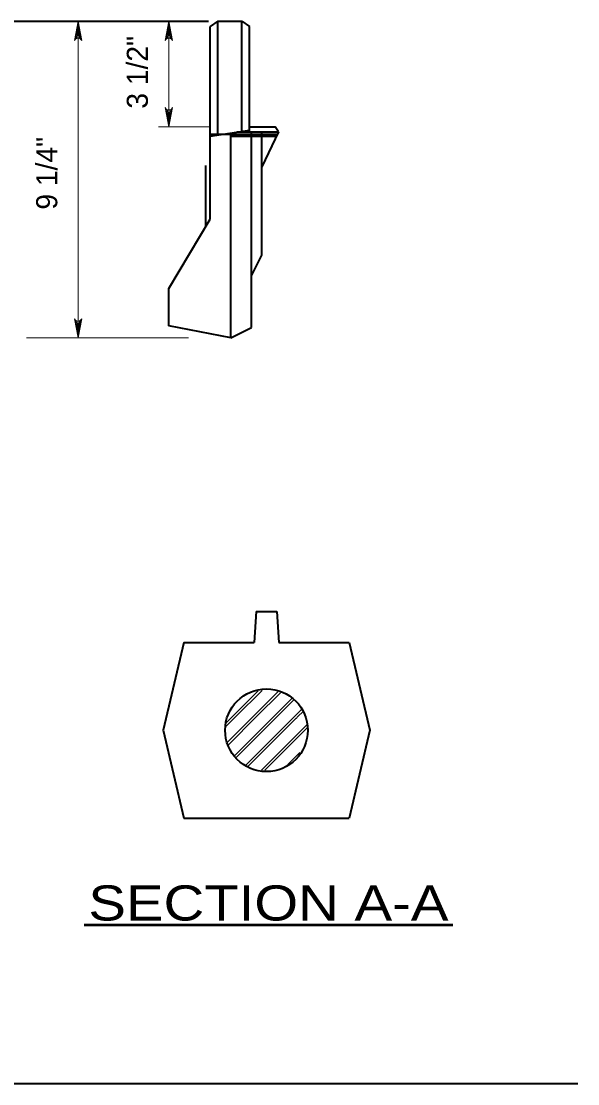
# Model space of a CAD drawing. Extents: x 15 to 140, y -57 to 117.
# Drawn here: x 113.5 to 140.4, y 57.9 to 109.4 of the extents above; entities that cross this region are included whole.
import ezdxf
from ezdxf.enums import TextEntityAlignment as Align

# ---------------------------------------------------------------- set-up
doc = ezdxf.new("R2010")
doc.units = 0
doc.header["$LTSCALE"] = 0.41
for name, color, linetype, lineweight in [('1', 7, 'Continuous', 35), ('10', 7, 'Continuous', 13), ('12', 7, 'Continuous', 53), ('13', 7, 'Continuous', 53), ('6', 7, 'Continuous', 13)]:
    doc.layers.add(name, color=color, linetype=linetype, lineweight=lineweight)

msp = doc.modelspace()

# ---------------------------------------------------------------- linework, layer by layer
at = {"layer": '1'}
for p, q in [((112.8121, 109.3527), (122.5672, 109.3527)), ((123.0195, 109.3532), (124.1695, 109.3532)), ((124.1695, 103.997), (124.1695, 109.3532)), ((124.1695, 109.3532), (124.5445, 109.1032)), ((124.5445, 103.997), (124.5445, 109.1032)), ((122.6445, 103.797), (124.5445, 104.0905)), ((122.6445, 103.897), (125.907, 103.897)), ((123.6445, 94.0282), (123.6445, 103.9515)), ((123.9389, 103.997), (125.955, 103.997)), ((124.5445, 104.247), (125.7917, 104.247)), ((124.6445, 94.5282), (124.6445, 103.997)), ((125.1445, 98.0282), (125.1445, 103.997)), ((125.955, 103.997), (125.1445, 102.3085)), ((125.955, 103.997), (125.7917, 104.247)), ((123.6445, 103.797), (125.859, 103.797)), ((122.4292, 99.4161), (122.4292, 102.3744)), ((120.6445, 96.415), (122.6445, 99.7782)), ((124.6445, 97.0282), (125.1445, 98.0282)), ((120.6445, 94.6114), (120.6445, 96.415)), ((123.6445, 94.0282), (120.6445, 94.6114)), ((123.6445, 94.0282), (124.6445, 94.5282)), ((124.8665, 80.799), (124.7665, 79.299)), ((124.8665, 80.799), (125.8665, 80.799)), ((125.8665, 80.799), (125.9665, 79.299)), ((121.3665, 79.299), (124.7665, 79.299)), ((125.9665, 79.299), (129.3665, 79.299)), ((121.3665, 70.799), (129.3665, 70.799)), ((140.4342, 57.946), (15.0728, 57.946))]:
    msp.add_line(p, q, dxfattribs=at)
for points in [[(123.0195, 103.897), (123.0195, 109.3532), (122.6445, 109.1032)], [(122.6445, 99.7782), (122.6445, 103.997), (122.6445, 109.1032)], [(121.3665, 79.299), (120.3665, 75.049), (121.3665, 70.799)], [(129.3665, 79.299), (130.3665, 75.049), (129.3665, 70.799)]]:
    msp.add_lwpolyline(points, dxfattribs=at)
msp.add_circle((125.3665, 75.049), 2, dxfattribs=at)
at = {"layer": '10'}
for p, q in [((116.2471, 94.0282), (116.2471, 109.3527)), ((120.6445, 104.247), (120.6445, 109.3527)), ((122.6445, 104.247), (120.1445, 104.247)), ((113.7471, 94.0282), (121.5976, 94.0282))]:
    msp.add_line(p, q, dxfattribs=at)
for points in [[(116.2471, 109.3527), (116.4219, 108.4206), (116.3721, 108.4924), (116.3096, 108.5294), (116.2471, 108.5402), (116.1846, 108.5294), (116.1221, 108.4924), (116.0723, 108.4206), (116.2471, 109.3527), (116.1221, 108.4924), (116.1846, 108.5294), (116.2471, 109.3527), (116.2471, 108.5402), (116.3096, 108.5294), (116.2471, 109.3527), (116.3721, 108.4924)], [(120.6445, 109.3527), (120.8193, 108.4206), (120.7695, 108.4924), (120.707, 108.5294), (120.6445, 108.5402), (120.582, 108.5294), (120.5195, 108.4924), (120.4697, 108.4206), (120.6445, 109.3527), (120.5195, 108.4924), (120.582, 108.5294), (120.6445, 109.3527), (120.6445, 108.5402), (120.707, 108.5294), (120.6445, 109.3527), (120.7695, 108.4924)], [(120.6445, 104.247), (120.4697, 105.179), (120.5195, 105.1072), (120.582, 105.0702), (120.6445, 105.0595), (120.707, 105.0702), (120.7695, 105.1072), (120.8193, 105.179), (120.6445, 104.247), (120.7695, 105.1072), (120.707, 105.0702), (120.6445, 104.247), (120.6445, 105.0595), (120.582, 105.0702), (120.6445, 104.247), (120.5195, 105.1072)], [(116.2471, 94.0282), (116.0723, 94.9603), (116.1221, 94.8885), (116.1846, 94.8514), (116.2471, 94.8407), (116.3096, 94.8514), (116.3721, 94.8885), (116.4219, 94.9603), (116.2471, 94.0282), (116.3721, 94.8885), (116.3096, 94.8514), (116.2471, 94.0282), (116.2471, 94.8407), (116.1846, 94.8514), (116.2471, 94.0282), (116.1221, 94.8885)]]:
    msp.add_lwpolyline(points, dxfattribs=at)
at = {"layer": '12'}
msp.add_line((116.5372, 65.6308), (134.3858, 65.6308), dxfattribs=at)
at = {"layer": '6'}
for p, q in [((123.7184, 75.7101), (124.9577, 76.9494)), ((123.8851, 75.7101), (125.1538, 76.9788)), ((124.7184, 75.7101), (125.9197, 76.9114)), ((124.8851, 75.7101), (126.0426, 76.8676)), ((125.7184, 75.7101), (126.5928, 76.5844)), ((125.8851, 75.7101), (126.6721, 76.4971)), ((123.4059, 75.3975), (123.7184, 75.7101)), ((123.4141, 75.2391), (123.8851, 75.7101)), ((123.4607, 74.4523), (124.7184, 75.7101)), ((123.5234, 74.3484), (124.8851, 75.7101)), ((123.8371, 73.8287), (125.7184, 75.7101)), ((123.8998, 73.7248), (125.8851, 75.7101)), ((124.7184, 73.7101), (126.7184, 75.7101)), ((124.8851, 73.7101), (126.8017, 75.6267)), ((126.7184, 75.7101), (126.8017, 75.7934)), ((126.8887, 75.7101), (126.8017, 75.623)), ((126.8054, 75.7934), (127.0703, 76.0583)), ((126.8887, 75.7101), (127.1382, 75.9595)), ((126.8054, 74.7934), (127.3053, 75.2932)), ((127.3387, 75.16), (126.8054, 74.6267)), ((125.7184, 73.7101), (126.8017, 74.7934)), ((125.8851, 73.7101), (126.8017, 74.6267)), ((124.3843, 73.376), (124.7184, 73.7101)), ((124.4889, 73.3139), (124.8851, 73.7101)), ((125.1263, 73.1179), (125.7184, 73.7101)), ((125.2857, 73.1107), (125.8851, 73.7101)), ((126.4024, 73.394), (126.7184, 73.7101)), ((126.7184, 73.7101), (126.8017, 73.7934)), ((126.8054, 73.7934), (126.978, 73.966))]:
    msp.add_line(p, q, dxfattribs=at)

# ---------------------------------------------------------------- texts
at = {"layer": '12', "width": 1.2}
msp.add_text('SECTION A-A', height=1.7, dxfattribs=at).set_placement((125.4615, 65.8433), align=Align.CENTER)
at = {"layer": '13'}
for s, p in [('3 1/2"', (119.6261, 106.8828)), ('9 1/4"', (115.2404, 101.9979))]:
    msp.add_text(s, height=1.02, rotation=90, dxfattribs=at).set_placement(p, align=Align.CENTER)

doc.saveas('drawing.dxf')
